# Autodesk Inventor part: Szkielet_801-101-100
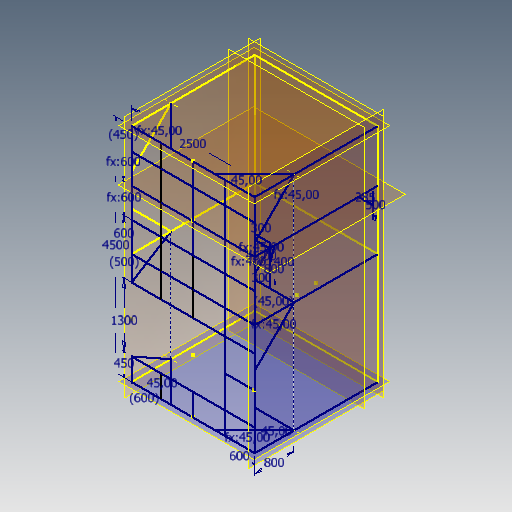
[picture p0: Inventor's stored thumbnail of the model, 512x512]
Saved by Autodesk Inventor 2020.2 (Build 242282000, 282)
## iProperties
Created: 2011-01
Part Number: Szkielet_801-101-100
Document SubType Name: Modeling
Designer: F.Stasiak
Density: 1 g/cm^3
Material: Ogólny
Appearance: Domyślna
Catalog Web Link: www.expertbooks.pl
Company: Fabian Stasiak CAD Consulting
Manager: www.cadconsulting.pl
Author: F.Stasiak
Subject: Zbiór ćwiczeń. Autodesk Inventor 2020. Kurs Professional
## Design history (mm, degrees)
sketch "Szkic9"
  geometry: L1 (1250, -1100)-(-1250, -1100); L2 (-1250, -1100)-(-1250, -650); L3 (-1250, 3400)-(1250, 3400); L4 (1250, -650)-(-1250, -650); L5 (1250, 650)-(-1250, 650); L6 (0, -1100)-(0, -650); L7 (650, -650)-(650, 650); L8 (650, 0)-(1250, 0); L9 (650, -650)-(650, -1100); L10 (-650, -650)-(-650, -1100); L11 (-1250, 1150)-(1250, 1150); L12 (-1250, 1750)-(1250, 1750); L13 (-1250, 2350)-(1250, 2350); L14 (-1250, 2950)-(1250, 2950); L15 (650, 650)-(650, 1150); L16 (650, 1150)-(650, 1750); L17 (650, 1750)-(650, 2350); L18 (650, 2350)-(650, 2950); L19 (650, 2950)-(650, 3400); L20 (0, 3400)-(0, 2950); L21 (0, 2950)-(0, 2350); L22 (0, 2350)-(0, 1750); L23 (0, 1750)-(0, 1150); L24 (0, 1150)-(0, 650); L25 (-650, 650)-(-650, 1150); L26 (-650, 1150)-(-650, 1750); L27 (-650, 1750)-(-650, 2350); L28 (-650, 2350)-(-650, 2950); L29 (-650, 2950)-(-650, 3400); L30 (-1250, 650)-(-1250, 3400); L31 (1250, 1950)-(1550, 1950); L32 (1550, 1950)-(1550, 2750); L33 (1550, 2750)-(1250, 2750); 1 further point
  constraints: 66 end point, 22 point on line, 21 perpendicular, 9 midpoint, 5 horizontal, 2 parallel, 2 vertical, 1 horizontal alignment, 1 vertical alignment, 12 other
  dimensions: "d28" = 2500 distance of L3.start L3.end; "d29" = 4500 distance of L1.end L3.start; "d30" = 1300 distance between parallel lines of L4 L5; "d31" = 450 distance between parallel lines of L4 L1; "d33" = 500 distance between parallel lines of L11 L5 (derived); "d34" = 600 distance between parallel lines of L12 L11; "d35" = 600 distance between parallel lines of L13 L12 (= d34); "d36" = 600 distance between parallel lines of L14 L13 (= d35); "d37" = 450 distance between parallel lines of L3 L14 (derived); "d38" = 600 dimension on L9; "d39" = 600 distance between parallel lines of L2 L10 (derived); "d53" = 300 distance of L31.start L31.end; "d54" = 800 distance of L31.end L32.end; "d55" = 400 distance between parallel lines of L13 L31 (= 0.5 x d54)
node "Płaszczyzna konstrukcyjna13"
sketch "Szkic10"
  geometry: L1 (-1250, 1150)-(1250, 1150) reference; L2 (1250, 3400)-(1250, -1100) reference; L3 (1250, -1100)-(-1250, -1100) reference; L4 (-1250, -1100)-(-1250, 3400) reference; L5 (-1250, 3400)-(1250, 3400) reference; 1 further point
node "Płaszczyzna konstrukcyjna14"
sketch "Szkic11"
  geometry: L1 (0, 0)-(4500, 0) reference; L2 (4500, 2500)-(4500, 0); L3 (2250, 2500)-(2250, 0); L4 (0, 2500)-(0, 0); L5 (4500, 1700)-(3700, 2500); L6 (2250, 1700)-(3050, 2500); L7 (2250, 1700)-(1450, 2500); L8 (0, 1700)-(800, 2500); L9 (4500, 1700)-(0, 1700); L10 (1050, 2500)-(1050, 0); L11 (1050, 2200)-(1350, 2500); L12 (1050, 2200)-(750, 2500); 1 further point
  constraints: 22 end point, 5 point on line, 3 perpendicular, 2 midpoint, 2 parallel, 7 other
  dimensions: "d41" = 800 dimension on L5.start; "d42" = 45 deg angle of L2 L5; "d43" = 45 deg angle of L6 L3 (= d42); "d44" = 45 deg angle of L7 L3 (derived); "d45" = 45 deg angle of L4 L8 (= d42); "d50" = 45 deg angle of L11 L10; "d51" = 45 deg angle of L12 L10 (= d50); "d52" = 300 dimension on L11.start
node "Płaszczyzna konstrukcyjna15"
sketch "Szkic12"
  geometry: L1 (4500, 2500)-(4500, 0) reference; L2 (2250, 2500)-(2250, 0) reference; L3 (0, 2500)-(0, 0) reference; L4 (2250, 1700)-(3050, 2500) reference; L5 (4500, 1700)-(3700, 2500) reference; L6 (2250, 1700)-(1750, 2500); L7 (2250, 1700)-(0, 1700); L8 (0, 1700)-(450, 2500); 1 further point
  constraints: 6 end point, 1 perpendicular, 1 point on line
node "Płaszczyzna konstrukcyjna16"
sketch "Szkic13"
  geometry: L1 (0, 2500)-(0, 0) reference; L2 (800, 0)-(0, 800); L3 (800, 2500)-(0, 1700); 1 further point
  constraints: 4 end point, 2 point on line
  dimensions: "d46" = 45 deg angle of L1 L2; "d47" = 45 deg angle of L1 L3 (= d46)
node "Płaszczyzna konstrukcyjna17"
sketch "Szkic14"
  geometry: L1 (0, 2500)-(0, 0) reference; L2 (800, 0)-(0, 800); L3 (800, 2500)-(0, 1700); 1 further point
  constraints: 4 end point, 2 point on line
  dimensions: "d48" = 45 deg angle of L1 L2; "d49" = 45 deg angle of L1 L3 (= d48)
node "Płaszczyzna konstrukcyjna18"
sketch "Szkic15"
  geometry: L1 (0, 0)-(2500, 0) reference; L2 (0, -300)-(400, 0); 1 further point
  constraints: 2 end point, 1 point on line
  dimensions: "d57" = 400 horizontal distance of L2.start L2.end
node "Płaszczyzna konstrukcyjna19"
sketch "Szkic16"
  geometry: L1 (1250, 2350)-(1535, 2350); L2 (1535, 2100)-(1535, 2600); 1 further point
  constraints: 4 end point, 1 horizontal, 1 midpoint, 1 perpendicular
  dimensions: "d59" = 285 distance of L1.start L1.end; "d60" = 500 distance of L2.start L2.end
other parameters: "d56" = 0
